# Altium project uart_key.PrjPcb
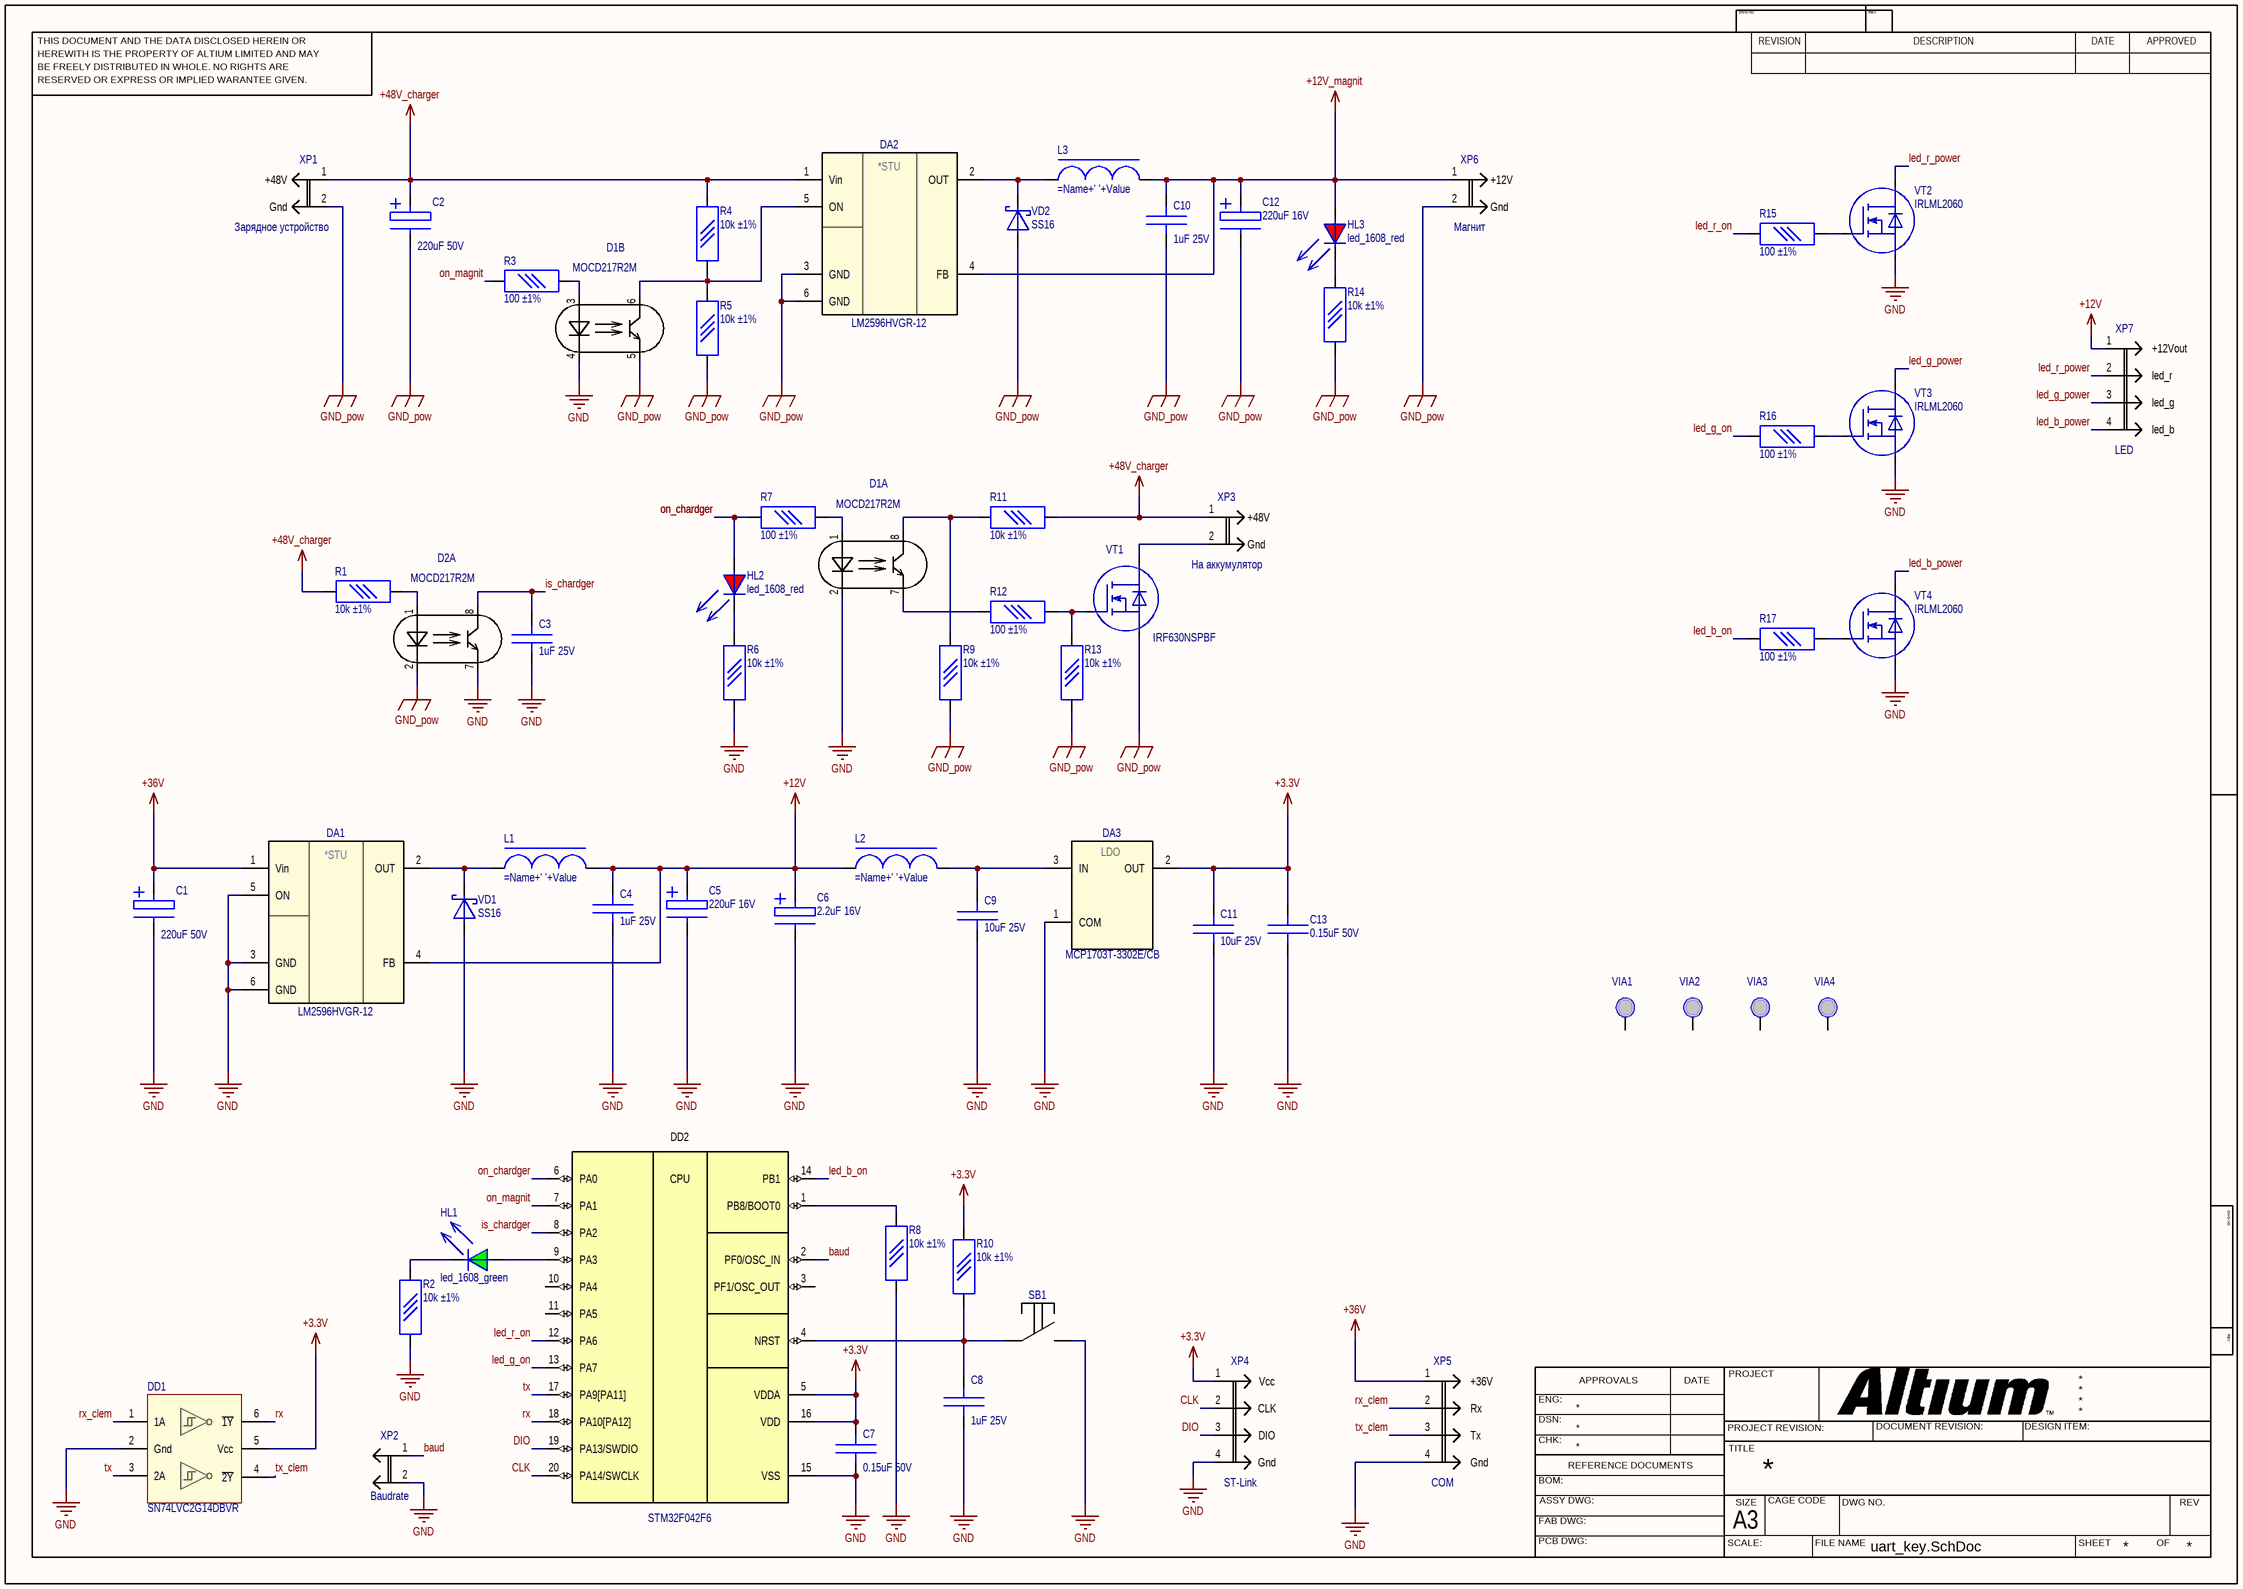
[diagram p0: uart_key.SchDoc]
1 sheet, 61 parts. Net scope: global (net labels, ports and power ports of the same name join across sheets).
Board file: uart_key.PcbDoc

## Sheet uart_key.SchDoc
size 420 x 297 mm

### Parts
C1  220uF 50V  [CAPAE_SMD_1010]
C2  220uF 50V  [CAPAE_SMD_1010]
C3  1uF 25V  [CC0603_0.8mm]
C4  1uF 25V  [CC0603_0.8mm]
C5  220uF 16V  [CAPAE_SMD_0607]
C6  2.2uF 16V  [TANT_3.2X1.6_A]
C7  0.15uF 50V  [CC0603_0.8mm]
C8  1uF 25V  [CC0603_0.8mm]
C9  10uF 25V  [CC0603_0.8mm]
C10  1uF 25V  [CC0603_0.8mm]
C11  10uF 25V  [CC0603_0.8mm]
C12  220uF 16V  [CAPAE_SMD_0607]
C13  0.15uF 50V  [CC0603_0.8mm]
D1  MOCD217R2M  [SO-8_height]  (parts A,B of 2)
D2  MOCD217R2M  [SO-8_height]  (part A of 2)
DA1  LM2596HVGR-12  [TO-263-5 (D2PAK)_2]
DA2  LM2596HVGR-12  [TO-263-5 (D2PAK)_2]
DA3  MCP1703T-3302E/CB  [SOT-23A_MCP]
DD1  SN74LVC2G14DBVR  [SOT-23-6]
DD2  STM32F042F6  [TSSOP-20_ST]
HL1  led_1608_green  [led_1608]
HL2  led_1608_red  [led_1608]
HL3  led_1608_red  [led_1608]
L1  (no value)  [SDR1006]
L2  (no value)  [LQH43C]
L3  (no value)  [SDR1006]
R1  10k ±1%  [R0603]
R2  10k ±1%  [R0603]
R3  100 ±1%  [R0603]
R4  10k ±1%  [R0603]
R5  10k ±1%  [R0603]
R6  10k ±1%  [R0603]
R7  100 ±1%  [R0603]
R8  10k ±1%  [R0603]
R9  10k ±1%  [R0603]
R10  10k ±1%  [R0603]
R11  10k ±1%  [R0603]
R12  100 ±1%  [R0603]
R13  10k ±1%  [R0603]
R14  10k ±1%  [R0603]
R15  100 ±1%  [R0603]
R16  100 ±1%  [R0603]
R17  100 ±1%  [R0603]
SB1  KLS7-TS6604-4.3-180  [Tact_SMD_6x6h4.3]  (value not drawn)
VD1  SS16  [DO-214AC (SMA)]
VD2  SS16  [DO-214AC (SMA)]
VIA1  via_circle_2.2mm  [via_circle_2.2]  (value not drawn)
VIA2  via_circle_2.2mm  [via_circle_2.2]  (value not drawn)
VIA3  via_circle_2.2mm  [via_circle_2.2]  (value not drawn)
VIA4  via_circle_2.2mm  [via_circle_2.2]  (value not drawn)
VT1  IRF630NSPBF  [TO-263A (D2PAK)]
VT2  IRLML2060  [SOT-23]
VT3  IRLML2060  [SOT-23]
VT4  IRLML2060  [SOT-23]
XP1  Зарядное устройство  Circuit_1: +48V  Circuit_2: Gnd  [DG308x2]
XP2  Baudrate  [PLS-2]
XP3  На аккумулятор  Circuit_1: +48V  Circuit_2: Gnd  [DG308x2]
XP4  ST-Link  Circuit_1: Vcc  Circuit_2: CLK  Circuit_3: DIO  Circuit_4: Gnd  [B4B-ZR]
XP5  COM  Circuit_1: +36V  Circuit_2: Rx  Circuit_3: Tx  Circuit_4: Gnd  [JST_XH_B4B-XH-A_1x04_P2.50mm_Vertical]
XP6  Магнит  Circuit_1: +12V  Circuit_2: Gnd  [DG308x2]
XP7  LED  Circuit_1: +12Vout  Circuit_2: led_r  Circuit_3: led_g  Circuit_4: led_b  [JST_XH_B4B-XH-A_1x04_P2.50mm_Vertical]

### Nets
+3.3V: C7.1 C11.1 C13.1 DA3.2(OUT) DD1.5(Vcc) DD2.5(VDDA) DD2.16(VDD) R10.1(BOT) XP4.1
+12V: C4.1 C5.2(+) C6.2(+) DA1.4(FB) L1.2 L2.1 XP7.1
+12V_magnit: C10.1 C12.2(+) DA2.4(FB) HL3.2(A) L3.2 XP6.1
+36V: C1.2(+) DA1.1(Vin) XP5.1
+48V_charger: C2.2(+) DA2.1(Vin) R1.2(TOP) R4.1(BOT) R11.2(TOP) XP1.1 XP3.1
GND: C1.1(-) C3.2 C4.2 C5.1(-) C6.1(-) C7.2 C8.2 C9.2 C11.2 C13.2 D1.2 D1.4 D2.7 DA1.3(GND) DA1.5(ON) DA1.6 DA3.1(COM) DD1.2(Gnd) DD2.15(VSS) R2.2(TOP) R6.2(TOP) R8.1(BOT) SB1.NO VD1.2(A) VT2.2(S) VT3.2(S) VT4.2(S) XP2.2 XP4.4 XP5.4
GND_pow: C2.1(-) C10.2 C12.1(-) D1.5 D2.2 DA2.3(GND) DA2.6 R5.2(TOP) R9.2(TOP) R13.2(TOP) R14.2(TOP) VD2.2(A) VT1.3(S) XP1.2 XP6.2
baud: DD2.2(PF0/OSC_IN) XP2.1
CLK: DD2.20(PA14/SWCLK) XP4.2
DIO: DD2.19(PA13/SWDIO) XP4.3
is_chardger: C3.1 D2.8 DD2.8(PA2)
led_b_on: DD2.14(PB1) R17.1(BOT)
led_b_power: VT4.3(D) XP7.4
led_g_on: DD2.13(PA7) R16.1(BOT)
led_g_power: VT3.3(D) XP7.3
led_r_on: DD2.12(PA6) R15.1(BOT)
led_r_power: VT2.3(D) XP7.2
on_chardger: DD2.6(PA0) HL2.2(A) R7.1(BOT)
on_magnit: DD2.7(PA1) R3.1(BOT)
rx: DD1.6(~{1Y}) DD2.18(PA10[PA12])
rx_clem: DD1.1(1A) XP5.2
tx: DD1.3(2A) DD2.17(PA9[PA11])
tx_clem: DD1.4(~{2Y}) XP5.3
NetC8_1: C8.1 DD2.4(NRST) R10.2(TOP) SB1.COM
NetC9_1: C9.1 DA3.3(IN) L2.2
NetD1_1: D1.1 R7.2(TOP)
NetD1_3: D1.3 R3.2(TOP)
NetD1_6: D1.6 DA2.5(ON) R4.2(TOP) R5.1(BOT)
NetD1_7: D1.7 R12.1(BOT)
NetD1_8: D1.8 R9.1(BOT) R11.1(BOT)
NetD2_1: D2.1 R1.1(BOT)
NetDA1_2: DA1.2(OUT) L1.1 VD1.1(C)
NetDA2_2: DA2.2(OUT) L3.1 VD2.1(C)
NetDD2_1: DD2.1(PB8/BOOT0) R8.2(TOP)
NetDD2_9: DD2.9(PA3) HL1.2(A)
NetHL1_1: HL1.1(C) R2.1(BOT)
NetHL2_1: HL2.1(C) R6.1(BOT)
NetHL3_1: HL3.1(C) R14.1(BOT)
NetR12_2: R12.2(TOP) R13.1(BOT) VT1.1(G)
NetR15_2: R15.2(TOP) VT2.1(G)
NetR16_2: R16.2(TOP) VT3.1(G)
NetR17_2: R17.2(TOP) VT4.1(G)
NetVT1_2: VT1.2(D) XP3.2

Not connected (* = marked no-connect by the designer): DD2 3(PF1/OSC_OUT) 10(PA4) 11(PA5); VIA1 1(VIA?); VIA2 1(VIA?); VIA3 1(VIA?); VIA4 1(VIA?)

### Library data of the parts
C1 C2 C5 C6 C12 = Capacitor_elec: Type: Конденсатор электр.; Tolerance: ±10%
C3 C4 C7-C11 C13 = Capacitor: Type: Конденсатор керам.; Tolerance: ±10%
D1 D2 = MOCD217R2M: Type: Оптопара
DA3 = MCP1703T-3302E/CB: Value: 3.3V
DD2 = STM32F042F6: ARM-based 32-bit MCU, up to 32 KB Flash, crystal-less USB  FS 2.0, CAN, 8 timers, ADC & comm. interfaces, 2.0 - 3.6 V
HL1 = led_1608_green: Type: Светодиод
HL2 HL3 = led_1608_red: Type: Светодиод
L1 L3 = Inductor: Value: 33uH; Type: Индуктивность
L2 = Inductor: Value: 15uH; Type: Индуктивность
R1 R2 R4-R6 R8-R11 R13 R14 = Res_0603
R3 R7 R12 R15-R17 = Res_0603: Value: 100
SB1 = Tact_6х6х4.3_SMD
VD1 VD2 = SS16: Type: Диод Шоттки
VT1 = IRF630NSPBF: Type: MOSFET N-chanel
VT2-VT4 = IRLML2060: Type: MOSFET N-chanel
XP1 XP3 XP6 = DG308x2
XP2 = Conn_01_02pin
XP4 = B4B-ZR_conn_01x04_st_link
XP5 XP7 = JST_XH_B4B-XH-A_1x04_P2.50mm_Vertical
